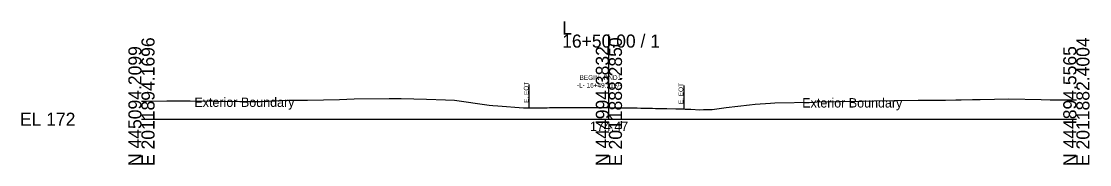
# Model space of a CAD drawing. Extents: x -26 to 4203, y -10 to 9526.
# Drawn here: x -25.7 to 202.8, y 6490.3 to 6520.9 of the extents above; entities that cross this region are included whole.
import ezdxf

# ---------------------------------------------------------------- set-up
doc = ezdxf.new("R2010")
doc.units = 0
for name, color, linetype in [('Default', 7, 'Continuous'), ('Exist Cross Section Cell', 7, 'Continuous'), ('Exist XS Center Line Elevation Label', 7, 'Continuous'), ('Exist XS Ground Line', 7, 'Continuous'), ('Prop XS Label Text', 7, 'Continuous'), ('Prop XS SE Text', 7, 'Continuous'), ('Scratch_Level_0', 7, 'Continuous')]:
    doc.layers.add(name, color=color, linetype=linetype)

msp = doc.modelspace()

# ---------------------------------------------------------------- linework, layer by layer
at = {"layer": 'Exist Cross Section Cell'}
for p, q in [((100, 6500), (100, 6518.09)), ((0, 6500), (100, 6500)), ((100, 6500), (200, 6500))]:
    msp.add_line(p, q, dxfattribs=at)
at = {"layer": 'Exist XS Ground Line'}
msp.add_lwpolyline([(0, 6503.88), (1.06, 6503.88), (5.46, 6503.93), (10.4, 6503.92), (15.48, 6503.88), (21.05, 6503.8), (25.49, 6503.8), (31.7, 6504.05), (35.51, 6504.1), (42.34, 6504.22), (45.53, 6504.35), (52.99, 6504.42), (55.55, 6504.4), (60.95, 6504.26), (65.06, 6504.13), (67, 6504.07), (74.36, 6503.03), (75.17, 6502.96), (76.22, 6502.88), (81.71, 6502.44), (82.27, 6502.45), (82.9, 6502.45), (84.31, 6502.46), (86.38, 6502.46), (86.81, 6502.46), (87.3, 6502.47), (89.32, 6502.5), (89.96, 6502.49), (91.81, 6502.48), (92.58, 6502.49), (94.04, 6502.51), (94.35, 6502.5), (95.3, 6502.49), (96.84, 6502.47), (97.94, 6502.47), (99.32, 6502.48), (100, 6502.47), (100.58, 6502.46), (101.8, 6502.44), (103.22, 6502.43), (104.3, 6502.43), (104.73, 6502.43), (105.08, 6502.43), (106.03, 6502.41), (106.83, 6502.38), (108.58, 6502.35), (109.34, 6502.34), (110, 6502.32), (111.84, 6502.28), (112.37, 6502.27), (114.32, 6502.22), (115.54, 6502.2), (116, 6502.19), (116.32, 6502.18), (117.19, 6502.15), (117.5, 6502.12), (119.48, 6502.01), (120.24, 6502.1), (120.83, 6502.1), (121.62, 6502.07), (122.1, 6502.11), (125.1, 6502.48), (130.11, 6503.09), (131.31, 6503.2), (134.54, 6503.44), (135.47, 6503.47), (143.86, 6503.67), (144.48, 6503.68), (154.01, 6503.89), (156.7, 6503.93), (161.02, 6503.99), (161.65, 6504), (166.17, 6504.08), (167.55, 6504.1), (170.13, 6504.06), (171.16, 6504.06), (171.99, 6504.07), (174.19, 6504.11), (175.35, 6504.14), (177.79, 6504.21), (179.4, 6504.22), (185.57, 6504.33), (192.49, 6504.21), (194.39, 6504.16), (200, 6504.13)], dxfattribs=at)
at = {"layer": 'Prop XS Label Text'}
for p, q in [((82.9, 6507.45), (82.9, 6502.45)), ((116, 6507.19), (116, 6502.19))]:
    msp.add_line(p, q, dxfattribs=at)

# ---------------------------------------------------------------- texts
at = {"layer": 'Default'}
msp.add_text('-', height=0.0001, dxfattribs=at).set_placement((0, 6500))
at = {"layer": 'Exist Cross Section Cell'}
for s, p in [('L', (90, 6518.09)), ('16+50.00 / 1', (90, 6515.29)), ('EL 172', (-26, 6498.6))]:
    msp.add_text(s, height=2.8, dxfattribs=at).set_placement(p)
for s, p in [('E 2011894.1696', (2.8, 6490)), ('E 2011888.2850', (102.8, 6490)), ('E 2011882.4004', (202.8, 6490)), ('N 445094.2099', (0, 6490)), ('N 444994.3832', (100, 6490)), ('N 444894.5565', (200, 6490))]:
    msp.add_text(s, height=2.8, rotation=90, dxfattribs=at).set_placement(p)
at = {"layer": 'Exist XS Center Line Elevation Label'}
msp.add_text('174.47', height=2, dxfattribs=at).set_placement((95.94, 6497.47))
at = {"layer": 'Prop XS Label Text'}
for p in [(82.8, 6503.48), (115.9, 6503.21)]:
    msp.add_text('E. EOT', height=1, rotation=90, dxfattribs=at).set_placement(p)
at = {"layer": 'Prop XS SE Text'}
for s, p in [('BEGIN -RND1-', (93.72, 6508.38)), ('-L- 16+49.51+/-', (93.15, 6506.76))]:
    msp.add_text(s, height=1, dxfattribs=at).set_placement(p)
at = {"layer": 'Scratch_Level_0'}
for p in [(11.32, 6502.63), (141.36, 6502.5)]:
    msp.add_text('Exterior Boundary', height=2, dxfattribs=at).set_placement(p)

doc.saveas('drawing.dxf')
